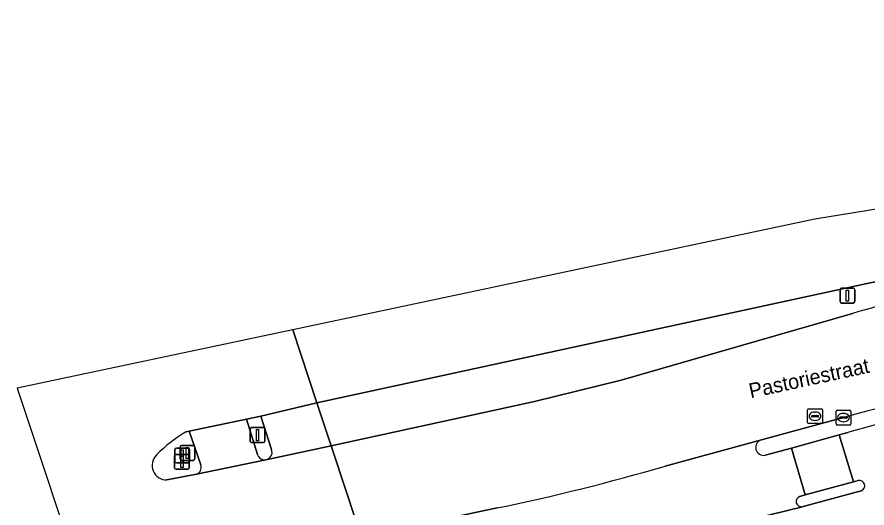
# Model space of a CAD drawing. Extents: x 160856 to 161310, y 384024 to 384878.
# Drawn here: x 160856.1 to 160913.4, y 384845 to 384878 of the extents above; entities that cross this region are included whole.
import ezdxf

# ---------------------------------------------------------------- set-up
doc = ezdxf.new("R2010")
doc.units = 0
for name, color, linetype in [('IMGEO_Berm_open', 7, 'Continuous'), ('IMGEO_Fietspad_gesloten', 7, 'Continuous'), ('IMGEO_Fietspad_open', 7, 'Continuous'), ('IMGEO_Kolk', 7, 'Continuous'), ('IMGEO_Lichtmast', 7, 'Continuous'), ('IMGEO_Openbare_ruimte_label', 7, 'Continuous'), ('IMGEO_Rijbaan_lokaal_open', 7, 'Continuous'), ('IMGEO_Rijbaan_regionaal_gesloten', 7, 'Continuous'), ('IMGEO_Rioolput', 7, 'Continuous'), ('IMGEO_Verkeerseiland_gesloten', 7, 'Continuous'), ('IMGEO_Verkeerseiland_open', 7, 'Continuous'), ('IMGEO_Verkeersregelinstallatiepaal', 7, 'Continuous'), ('IMGEO_Voetpad_open', 7, 'Continuous')]:
    doc.layers.add(name, color=color, linetype=linetype)

msp = doc.modelspace()

# ---------------------------------------------------------------- linework, layer by layer
at = {"layer": 'IMGEO_Berm_open'}
msp.add_lwpolyline([(160925.954, 384861.652), (160927.748, 384862.071), (160927.48, 384863.128), (160876.331, 384852.047), (160877.288, 384849.145), (160890.991, 384852.122), (160896.829, 384853.569), (160912.426, 384858.058)], dxfattribs=at)
msp.add_arc((161004.737, 384537.85), 333.248, 103.67478, 106.08153, dxfattribs=at)
at = {"layer": 'IMGEO_Fietspad_gesloten'}
for points in [[(160912.11, 384850.05), (160911.529, 384849.89), (160912.478, 384846.734), (160912.793, 384846.82)], [(160912.998, 384846.117), (160909.09, 384845.067), (160909.039, 384845.055), (160901.087, 384843.098)]]:
    msp.add_lwpolyline(points, dxfattribs=at)
for centre, radius, start, end in [((161060.371, 384317.53), 552.774, 103.74361, 105.55791), ((160912.878, 384846.464), 0.367, 289.0314, 103.4828)]:
    msp.add_arc(centre, radius, start, end, dxfattribs=at)
at = {"layer": 'IMGEO_Fietspad_open'}
for points in [[(160871.583, 384850.934), (160867.72, 384850.135), (160868.516, 384847.862)], [(160872.328, 384848.57), (160871.583, 384850.934)], [(160868.218, 384847.236), (160872.902, 384848.21)]]:
    msp.add_lwpolyline(points, dxfattribs=at)
for centre, radius, start, end in [((160872.825, 384848.726), 0.521, 197.3617, 278.4483), ((160868.038, 384847.706), 0.503, 290.9629, 18.1246)]:
    msp.add_arc(centre, radius, start, end, dxfattribs=at)
at = {"layer": 'IMGEO_Kolk'}
for p, q in [((160911.305, 384850.624), (160911.305, 384851.476)), ((160911.38, 384851.55), (160912.232, 384851.55)), ((160911.793, 384851.33), (160911.818, 384851.33)), ((160912.306, 384851.476), (160912.306, 384850.624)), ((160911.564, 384851.044), (160911.564, 384851.056)), ((160912.002, 384851.007), (160911.604, 384851.007)), ((160911.607, 384851.093), (160912.005, 384851.093)), ((160911.816, 384850.77), (160911.791, 384850.77)), ((160912.048, 384851.056), (160912.048, 384851.044)), ((160912.232, 384850.55), (160911.38, 384850.55))]:
    msp.add_line(p, q, dxfattribs=at)
for points in [[(160911.305, 384850.624), (160911.305, 384851.476)], [(160911.38, 384851.55), (160912.232, 384851.55)], [(160912.306, 384851.476), (160912.306, 384850.624)], [(160912.232, 384850.55), (160911.38, 384850.55)]]:
    msp.add_lwpolyline(points, dxfattribs=at)
for centre, radius, start, end in [((160911.382, 384851.474), 0.0765, 91.552, 178.448), ((160911.382, 384851.474), 0.0765, 91.552, 178.448), ((160912.23, 384851.474), 0.0765, 1.552, 88.448), ((160912.23, 384851.474), 0.0765, 1.552, 88.448), ((160911.382, 384850.626), 0.0765, 181.552, 268.448), ((160911.382, 384850.626), 0.0765, 181.552, 268.448), ((160911.604, 384851.053), 0.0403, 85.8775, 175.7526), ((160911.601, 384851.043), 0.0366, 178.938, 274.7102), ((160912.005, 384851.05), 0.043, 264.8664, 352.4533), ((160912.009, 384851.055), 0.0386, 1.7309, 96.639), ((160912.23, 384850.626), 0.0765, 271.552, 358.448), ((160912.23, 384850.626), 0.0765, 271.552, 358.448)]:
    msp.add_arc(centre, radius, start, end, dxfattribs=at)
for centre, major_axis, ratio, start_param, end_param in [((160911.792, 384851.05), (-0.387, 0.002), 0.722429, 4.712389, 7.853982), ((160911.817, 384851.05), (-0.39, 0.002), 0.717154, 1.570796, 4.712389)]:
    msp.add_ellipse(centre, major_axis=major_axis, ratio=ratio, start_param=start_param, end_param=end_param, dxfattribs=at)
at = {"layer": 'IMGEO_Lichtmast'}
for p, q in [((160911.575, 384858.857), (160911.575, 384859.657)), ((160911.575, 384859.657), (160911.575, 384858.857)), ((160911.675, 384859.757), (160912.465, 384859.757)), ((160912.465, 384859.757), (160911.675, 384859.757)), ((160912.565, 384859.657), (160912.565, 384858.857)), ((160912.565, 384858.857), (160912.565, 384859.657)), ((160912.465, 384858.757), (160911.675, 384858.757)), ((160911.675, 384858.757), (160912.465, 384858.757)), ((160866.745, 384847.67), (160866.745, 384848.47)), ((160866.745, 384848.47), (160866.745, 384847.67)), ((160866.845, 384848.57), (160867.635, 384848.57)), ((160867.635, 384848.57), (160866.845, 384848.57)), ((160867.735, 384848.47), (160867.735, 384847.67)), ((160867.735, 384847.67), (160867.735, 384848.47)), ((160867.635, 384847.57), (160866.845, 384847.57)), ((160866.845, 384847.57), (160867.635, 384847.57))]:
    msp.add_line(p, q, dxfattribs=at)
for points in [[(160911.995, 384859.632), (160912.145, 384859.632), (160912.145, 384858.882), (160911.995, 384858.882), (160911.995, 384859.632)], [(160867.165, 384848.445), (160867.315, 384848.445), (160867.315, 384847.695), (160867.165, 384847.695), (160867.165, 384848.445)]]:
    msp.add_lwpolyline(points, dxfattribs=at)
for centre, start, end in [((160911.675, 384859.657), 90, 180), ((160911.675, 384859.657), 90, 180), ((160912.465, 384859.657), 0, 90), ((160912.465, 384859.657), 360, 90), ((160911.675, 384858.857), 180, 270), ((160911.675, 384858.857), 180, 270), ((160912.465, 384858.857), 270, 0), ((160912.465, 384858.857), 270, 0), ((160866.845, 384848.47), 90, 180), ((160866.845, 384848.47), 90, 180), ((160867.635, 384848.47), 0, 90), ((160867.635, 384848.47), 360, 90), ((160866.845, 384847.67), 180, 270), ((160866.845, 384847.67), 180, 270), ((160867.635, 384847.67), 270, 0), ((160867.635, 384847.67), 270, 0)]:
    msp.add_arc(centre, 0.1, start, end, dxfattribs=at)
at = {"layer": 'IMGEO_Rijbaan_lokaal_open'}
for points in [[(160906.279, 384849.554), (160899.794, 384847.787)], [(160908.866, 384845.747), (160909.221, 384845.844), (160908.299, 384849.002), (160906.533, 384848.516)], [(160888.476, 384844.968), (160879.317, 384843.024), (160884.239, 384843.358), (160888.981, 384843.664)], [(160901.087, 384843.098), (160909.039, 384845.055)]]:
    msp.add_lwpolyline(points, dxfattribs=at)
msp.add_lwpolyline([(160911.529, 384849.89), (160908.299, 384849.002), (160909.221, 384845.844), (160912.478, 384846.734)], close=True, dxfattribs=at)
for centre, radius, start, end in [((160906.429, 384849.041), 0.535, 106.3189, 281.1814), ((160858.986, 384987.495), 145.546, 281.68981, 286.2826), ((160908.979, 384845.408), 0.358, 108.4318, 279.6407)]:
    msp.add_arc(centre, radius, start, end, dxfattribs=at)
at = {"layer": 'IMGEO_Rijbaan_regionaal_gesloten'}
for points in [[(161159.494, 384865.813), (161169.487, 384866.328), (161180.477, 384866.898), (161204.609, 384868.254), (161229.619, 384869.602), (161254.541, 384870.979), (161254.166, 384874.428), (161167.157, 384868.815), (161117.456, 384869.429), (161022.134, 384878.002), (161020.709, 384877.941), (160983.645, 384876.362), (160971.848, 384874.449), (160909.879, 384864.4), (160874.71, 384856.965)], [(160874.71, 384856.965), (160876.331, 384852.047), (160927.48, 384863.128), (160950.387, 384867.981), (160951.392, 384868.17), (160958.365, 384869.618), (160965.245, 384871.006)], [(160912.426, 384858.058), (160896.829, 384853.569), (160890.991, 384852.122), (160877.288, 384849.145), (160878.351, 384845.96), (160879.317, 384843.024), (160888.476, 384844.968)], [(160867.532, 384850.092), (160867.72, 384850.135), (160871.583, 384850.934), (160872.553, 384851.156), (160876.331, 384852.047), (160874.71, 384856.965), (160856.132, 384853.037), (160860.695, 384839.343)], [(160899.794, 384847.787), (160906.279, 384849.554), (160911.806, 384851.05)], [(160879.317, 384843.024), (160878.351, 384845.96), (160877.288, 384849.145), (160872.902, 384848.21), (160868.218, 384847.236), (160866.232, 384846.852)]]:
    msp.add_lwpolyline(points, dxfattribs=at)
for centre, radius, start, end in [((161004.737, 384537.85), 333.248, 103.67478, 106.08153), ((161111.9, 384121.418), 756.572, 104.011306, 105.335745), ((160872.412, 384841.752), 9.663, 120.3334, 135.3649), ((160866.212, 384847.832), 0.98, 133.6074, 271.1836), ((160858.986, 384987.495), 145.546, 281.68981, 286.2826)]:
    msp.add_arc(centre, radius, start, end, dxfattribs=at)
at = {"layer": 'IMGEO_Rioolput'}
for p, q in [((160909.392, 384850.717), (160909.392, 384851.569)), ((160909.467, 384851.643), (160910.319, 384851.643)), ((160909.694, 384851.186), (160910.092, 384851.186)), ((160909.88, 384851.423), (160909.905, 384851.423)), ((160910.393, 384851.569), (160910.393, 384850.717)), ((160910.319, 384850.643), (160909.467, 384850.643)), ((160909.651, 384851.137), (160909.651, 384851.149)), ((160910.089, 384851.1), (160909.691, 384851.1)), ((160909.903, 384850.863), (160909.878, 384850.863)), ((160910.135, 384851.149), (160910.135, 384851.137))]:
    msp.add_line(p, q, dxfattribs=at)
for points in [[(160909.392, 384850.717), (160909.392, 384851.569)], [(160909.467, 384851.643), (160910.319, 384851.643)], [(160910.393, 384851.569), (160910.393, 384850.717)], [(160910.319, 384850.643), (160909.467, 384850.643)]]:
    msp.add_lwpolyline(points, dxfattribs=at)
for centre, radius, start, end in [((160909.469, 384851.567), 0.0765, 91.552, 178.448), ((160909.469, 384851.567), 0.0765, 91.552, 178.448), ((160909.691, 384851.146), 0.0403, 85.8775, 175.7526), ((160910.096, 384851.148), 0.0386, 1.7309, 96.639), ((160910.317, 384851.567), 0.0765, 1.552, 88.448), ((160910.317, 384851.567), 0.0765, 1.552, 88.448), ((160909.469, 384850.719), 0.0765, 181.552, 268.448), ((160909.469, 384850.719), 0.0765, 181.552, 268.448), ((160909.688, 384851.136), 0.0366, 178.938, 274.7102), ((160910.092, 384851.143), 0.043, 264.8664, 352.4533), ((160910.317, 384850.719), 0.0765, 271.552, 358.448), ((160910.317, 384850.719), 0.0765, 271.552, 358.448)]:
    msp.add_arc(centre, radius, start, end, dxfattribs=at)
for centre, major_axis, ratio, start_param, end_param in [((160909.879, 384851.143), (-0.387, 0.002), 0.722429, 4.712389, 7.853982), ((160909.904, 384851.143), (-0.39, 0.002), 0.717154, 1.570796, 4.712389)]:
    msp.add_ellipse(centre, major_axis=major_axis, ratio=ratio, start_param=start_param, end_param=end_param, dxfattribs=at)
at = {"layer": 'IMGEO_Verkeerseiland_gesloten'}
for points in [[(160911.806, 384851.05), (160906.279, 384849.554)], [(160906.533, 384848.516), (160908.299, 384849.002), (160911.529, 384849.89), (160912.11, 384850.05)], [(160912.793, 384846.82), (160912.478, 384846.734), (160909.221, 384845.844), (160908.866, 384845.747)], [(160909.039, 384845.055), (160909.09, 384845.067), (160912.998, 384846.117)]]:
    msp.add_lwpolyline(points, dxfattribs=at)
for centre, radius, start, end in [((161111.9, 384121.418), 756.572, 104.011306, 105.335745), ((161060.371, 384317.53), 552.774, 103.74361, 105.55791), ((160906.429, 384849.041), 0.535, 106.3189, 281.1814), ((160912.878, 384846.464), 0.367, 289.0314, 103.4828), ((160908.979, 384845.408), 0.358, 108.4318, 279.6407)]:
    msp.add_arc(centre, radius, start, end, dxfattribs=at)
at = {"layer": 'IMGEO_Verkeerseiland_open'}
for points in [[(160873.287, 384848.904), (160872.553, 384851.156), (160871.583, 384850.934), (160872.328, 384848.57)], [(160868.516, 384847.862), (160867.72, 384850.135), (160867.532, 384850.092)], [(160866.232, 384846.852), (160868.218, 384847.236)]]:
    msp.add_lwpolyline(points, dxfattribs=at)
for centre, radius, start, end in [((160872.412, 384841.752), 9.663, 120.3334, 135.3649), ((160872.768, 384848.738), 0.545, 284.2409, 17.72), ((160866.212, 384847.832), 0.98, 133.6074, 271.1836), ((160872.825, 384848.726), 0.521, 197.3617, 278.4483), ((160868.038, 384847.706), 0.503, 290.9629, 18.1246)]:
    msp.add_arc(centre, radius, start, end, dxfattribs=at)
at = {"layer": 'IMGEO_Verkeersregelinstallatiepaal'}
for p, q in [((160871.835, 384849.472), (160871.835, 384850.272)), ((160871.835, 384850.272), (160871.835, 384849.472)), ((160871.935, 384850.372), (160872.725, 384850.372)), ((160872.725, 384850.372), (160871.935, 384850.372)), ((160872.825, 384850.272), (160872.825, 384849.472)), ((160872.825, 384849.472), (160872.825, 384850.272)), ((160866.767, 384848.096), (160866.767, 384848.896)), ((160866.767, 384848.896), (160866.767, 384848.096)), ((160866.867, 384848.996), (160867.657, 384848.996)), ((160867.657, 384848.996), (160866.867, 384848.996)), ((160867.115, 384848.273), (160867.115, 384849.073)), ((160867.115, 384849.073), (160867.115, 384848.273)), ((160867.215, 384849.173), (160868.005, 384849.173)), ((160868.005, 384849.173), (160867.215, 384849.173)), ((160867.757, 384848.896), (160867.757, 384848.096)), ((160867.757, 384848.096), (160867.757, 384848.896)), ((160868.105, 384849.073), (160868.105, 384848.273)), ((160868.105, 384848.273), (160868.105, 384849.073)), ((160872.725, 384849.372), (160871.935, 384849.372)), ((160871.935, 384849.372), (160872.725, 384849.372)), ((160867.657, 384847.996), (160866.867, 384847.996)), ((160866.867, 384847.996), (160867.657, 384847.996)), ((160868.005, 384848.173), (160867.215, 384848.173)), ((160867.215, 384848.173), (160868.005, 384848.173))]:
    msp.add_line(p, q, dxfattribs=at)
for points in [[(160872.255, 384850.247), (160872.405, 384850.247), (160872.405, 384849.497), (160872.255, 384849.497), (160872.255, 384850.247)], [(160867.535, 384849.048), (160867.685, 384849.048), (160867.685, 384848.298), (160867.535, 384848.298), (160867.535, 384849.048)], [(160867.187, 384848.871), (160867.337, 384848.871), (160867.337, 384848.121), (160867.187, 384848.121), (160867.187, 384848.871)]]:
    msp.add_lwpolyline(points, dxfattribs=at)
for centre, start, end in [((160871.935, 384850.272), 90, 180), ((160871.935, 384850.272), 90, 180), ((160872.725, 384850.272), 0, 90), ((160872.725, 384850.272), 360, 90), ((160871.935, 384849.472), 180, 270), ((160871.935, 384849.472), 180, 270), ((160872.725, 384849.472), 270, 0), ((160872.725, 384849.472), 270, 0), ((160866.867, 384848.896), 90, 180), ((160866.867, 384848.896), 90, 180), ((160867.215, 384849.073), 90, 180), ((160867.215, 384849.073), 90, 180), ((160867.657, 384848.896), 0, 90), ((160867.657, 384848.896), 360, 90), ((160868.005, 384849.073), 0, 90), ((160868.005, 384849.073), 360, 90), ((160866.867, 384848.096), 180, 270), ((160866.867, 384848.096), 180, 270), ((160867.215, 384848.273), 180, 270), ((160867.215, 384848.273), 180, 270), ((160867.657, 384848.096), 270, 0), ((160867.657, 384848.096), 270, 0), ((160868.005, 384848.273), 270, 0), ((160868.005, 384848.273), 270, 0)]:
    msp.add_arc(centre, 0.1, start, end, dxfattribs=at)
at = {"layer": 'IMGEO_Voetpad_open'}
msp.add_lwpolyline([(160872.902, 384848.21), (160877.288, 384849.145), (160876.331, 384852.047), (160872.553, 384851.156), (160873.287, 384848.904)], dxfattribs=at)
msp.add_arc((160872.768, 384848.738), 0.545, 284.2409, 17.72, dxfattribs=at)

# ---------------------------------------------------------------- texts
at = {"layer": 'IMGEO_Openbare_ruimte_label'}
msp.add_text('Pastoriestraat', height=1, rotation=12.1868, dxfattribs=at).set_placement((160905.556, 384852.343))

doc.saveas('drawing.dxf')
